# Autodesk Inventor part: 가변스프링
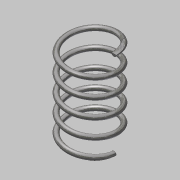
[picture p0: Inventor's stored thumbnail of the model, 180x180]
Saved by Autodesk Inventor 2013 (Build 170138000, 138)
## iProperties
Created: 2019-05
Part Number: 가변스프링
Material: 스테인리스강
Document SubType Name: Modeling
Designer: Administrator
Density: 8.08 g/cm^3
Mass: 7.87899 g
Surface Area: 19.733 cm^2
Volume: 0.975122 cm^3
Author: Administrator
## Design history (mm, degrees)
sketch "스케치1"
  geometry: L1 (0, 0)-(10, 0); L2 (10, 0)-(10, 34); L3 (10, 34)-(0, 34); L4 (0, 34)-(0, 0); C1 r 1 at (10, 0)
  constraints: 8 end point, 2 parallel, 1 centre point, 1 coincident, 1 horizontal, 1 perpendicular
  dimensions: "d0" = 2 diameter of C1; "d2" = 34 distance of L1.end L2.end (derived); "d3" = 20 diameter of L2 L4
feature "코일1" sketch "스케치1" pitch "d4" = 10; turns "d6" = 5; dims "d5" = 34 (= d2), "d7" = 0, angle "d8" = 90 deg, angle "d9" = 90 deg, "d10" = 0, "d11" = 0
sketch "스케치2"
  geometry: L1 (34, 11.5)-(0, 11.5); L2 (0, 11.5)-(0, -11.5); L3 (0, -11.5)-(34, -11.5); L4 (34, -11.5)-(34, 11.5); 2 further points
  constraints: 8 end point, 2 parallel, 1 coincident, 1 horizontal, 1 midpoint, 1 perpendicular
  dimensions: "d12" = 34 distance of L2.end L3.end (derived); "d14" = 23 distance between parallel lines of L3 L1
extrude "돌출1" sketch "스케치2" stored distance "d15" = 23; taper "d16" = 0 deg
node "솔리드1"
